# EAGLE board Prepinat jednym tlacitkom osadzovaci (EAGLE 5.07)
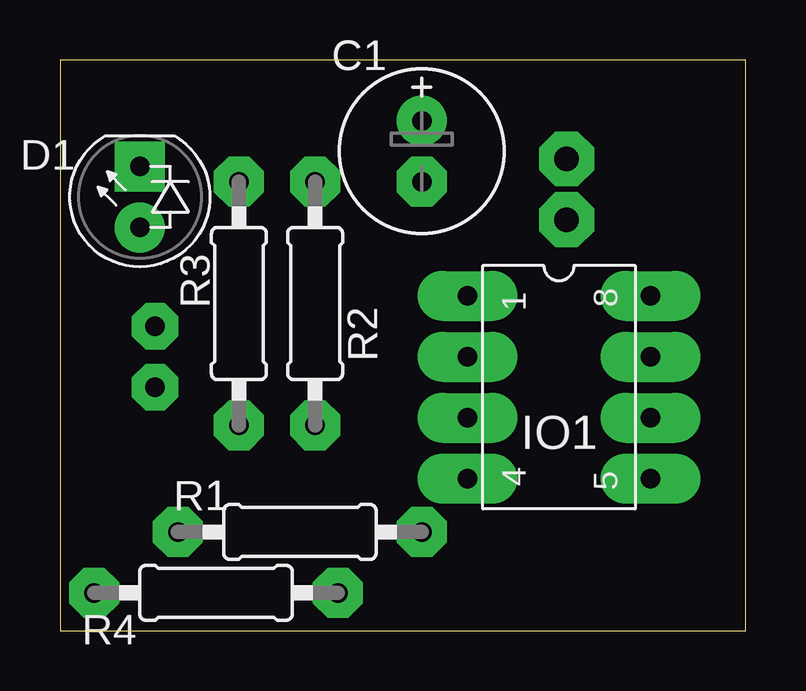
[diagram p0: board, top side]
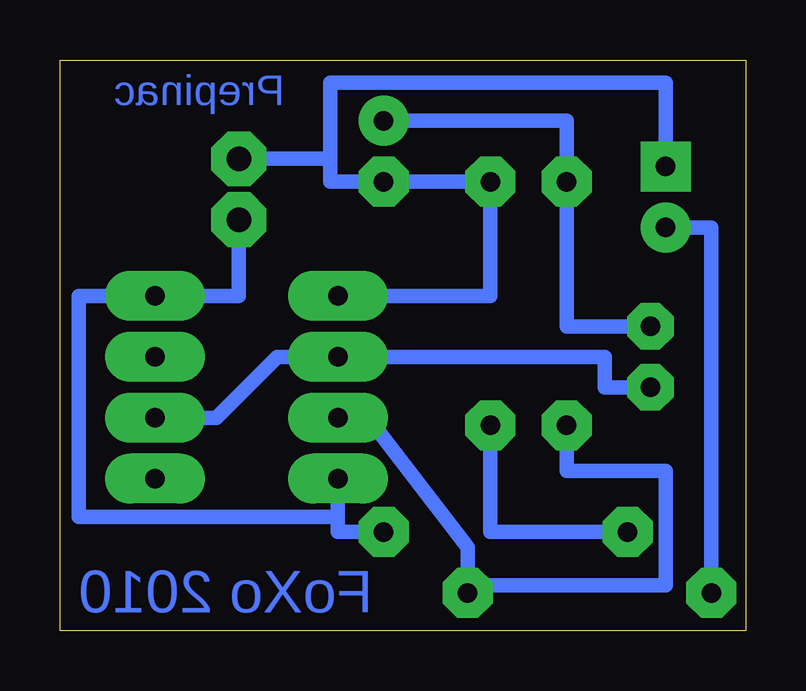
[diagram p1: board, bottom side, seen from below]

Size 28.56 x 23.8 mm. Coordinates in mm from the lower left corner, seen from the top.
Outline: 0,0 28.56,0 28.56,23.8 0,23.8 0,0
Copper layers (1*16): Top 0.035mm / dielectric 1.5mm / Bottom 0.035mm
Design rules "default *": minimum track width 10mil, minimum drill 24mil, track to track 8mil, track to pad 8mil, pad to pad 8mil, via to via 8mil, smd to smd 8mil, copper to edge 40mil, drill to drill 8mil, minimum pad ring 25mil, minimum via ring 8mil, stop-mask expansion 4mil, vias tented up to drill 0mil, thermal gap 10mil

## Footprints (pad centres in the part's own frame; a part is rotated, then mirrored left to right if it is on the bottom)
E2,5-7 = drill 0.813 pad 1.6 round: + -1.27,0 | drill 0.813 pad 1.6 octagon: - 1.27,0
LED_5 = drill 0.813 pad 1.778 round: A -1.27,0 | drill 0.813 pad 1.778 square: K 1.27,0
DIL8 = drill 0.813 pad 1.4 long: 1 -3.81,-3.81; 2 -1.27,-3.81; 3 1.27,-3.81; 4 3.81,-3.81; 5 3.81,3.81; 6 1.27,3.81; 7 -1.27,3.81; 8 -3.81,3.81
PAD_1 = drill 1.016 pad 2.184 octagon: 1 0,0
0207/10 = drill 0.813 octagon: 1 -5.08,0; 2 5.08,0

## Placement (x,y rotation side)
C1  1uF  [E2,5-7]  15.07,20 270 top
D1  LED_5  [LED_5]  3.33,18.09 90 top
IO1  555  [DIL8]  20.79,10.15 270 top
PAD1  + 12 V  [PAD_1]  21.11,17.14 90 top
PAD2  0V  [PAD_1]  21.11,19.68 90 top
R1  10K  [0207/10]  10,4.12 0 top
R2  10K  [0207/10]  10.63,13.65 90 top
R3  100K  [0207/10]  7.46,13.65 90 top
R4  470R  [0207/10]  6.5,1.58 180 top

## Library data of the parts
C1 R1-R4 = rcl
D1 IO1 PAD1 PAD2 = #PaJa_20

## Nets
N$1: IO1.2 IO1.6
N$2: C1.+
N$3: IO1.3 R3.1
N$4: C1.- D1.K IO1.1 R2.2
N$6: IO1.4
S$1: IO1.8
S$4: D1.A R4.2
S$6: R1.1

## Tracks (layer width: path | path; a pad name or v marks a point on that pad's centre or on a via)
N$1
  Bottom 0.61: IO1.6 22.06,8.88 19.52,11.42 IO1.2 5.87,11.42 5.87,10.15 4.92,10.15
N$2
  Bottom 0.61: C1.+ 7.46,21.27 7.46,12.69 4.92,12.69
N$3
  Bottom 0.61: 15.71,8.88 11.58,3.49 11.58,1.9 3.33,1.9 3.33,6.66 7.46,6.66 R3.1
  Bottom 0.813: 15.71,8.88 IO1.3
N$4
  Bottom 0.61: IO1.1 10.63,13.96 R2.2 C1.- 17.3,18.73 17.3,19.68 | 17.3,19.68 17.3,22.86 3.33,22.86 D1.K | 17.3,19.68 20.16,19.68
N$6
  Bottom 0.61: 16.98,4.76 IO1.4 | 16.98,4.76 27.77,4.76 | 15.71,4.12 16.98,4.12 16.98,4.76
S$1
  Bottom 0.61: IO1.8 27.77,13.96 27.77,4.76
S$2  (via drill 0.81 pad 1.93)
  other vias: 3.96,12.69
S$3  (via drill 0.81 pad 1.93)
  other vias: 3.96,10.15
S$4
  Bottom 0.61: R4.2 1.42,16.82 D1.A
S$5
  Bottom 0.61: 24.28,13.96 21.11,13.96 21.11,16.19
S$6
  Bottom 0.61: 10.63,8.57 10.63,4.12 R1.1

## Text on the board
Bottom: Prepinac | FoXo 2010
tOrigins: TL1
